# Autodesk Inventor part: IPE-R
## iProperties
Author: Jan-Steinar
Shininess: 20.0
PropertySet Name: _Private Model Information
Created: 2001-01
Part Number: IPE-R
Document SubType Name: Modeling
Designer: Jan-Steinar
Control State: 0
Master: False
Checked Out: False
PropertySet Name: Design Tracking Control
Density: 0.0
Volumn: 0.0
Area: 0.0
PropertySet Name: Model Information
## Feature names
1. Extrusion1
